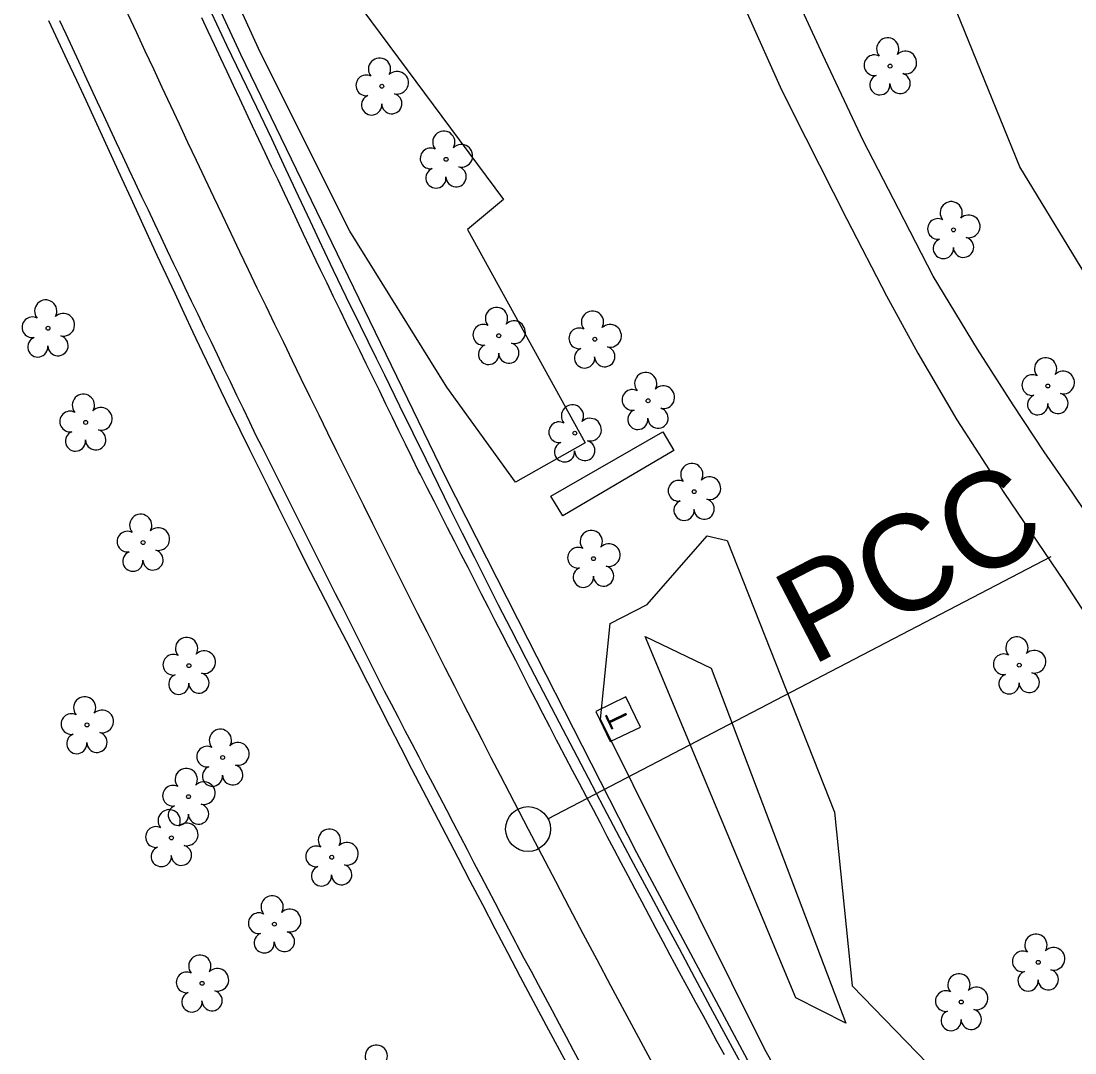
# Model space of a CAD drawing. Extents: x 474972 to 479313, y 498315 to 502691.
# Drawn here: x 475995.1 to 476171.4, y 501439.4 to 501612 of the extents above; entities that cross this region are included whole.
import ezdxf

# ---------------------------------------------------------------- set-up
doc = ezdxf.new("R2010")
doc.units = 0
for name, color, linetype in [('Exist Guardrail', 7, 'Continuous'), ('Exist Horizontal Alignment', 7, 'Continuous'), ('Exist Other Culture Area Outline', 7, 'Continuous'), ('Exist Roads EOP', 7, 'Continuous'), ('Exist Roads EOT', 7, 'Continuous'), ('Exist Roads Soil', 7, 'Continuous'), ('Exist Utilities Telephone Pedestal CELL', 7, 'Continuous'), ('Exist Vegetation Hedge Row', 7, 'Continuous'), ('Exist Vegetation Tree CELL', 7, 'Continuous'), ('Exist Vegetation Woods Line', 7, 'Continuous')]:
    doc.layers.add(name, color=color, linetype=linetype)

msp = doc.modelspace()

# ---------------------------------------------------------------- linework, layer by layer
at = {"layer": 'Exist Guardrail'}
msp.add_lwpolyline([(476022.76, 501626.04), (476031.8, 501606.5), (476046.22, 501576.76), (476066.08, 501535.85), (476079.91, 501508.65), (476098.09, 501472.91), (476116.59, 501438.31), (476140.29, 501395.78), (476158.27, 501364.42), (476168.54, 501347.18), (476182.34, 501324.79), (476193.05, 501307.85), (476195.59, 501304.15)], dxfattribs=at)
at = {"layer": 'Exist Horizontal Alignment'}
msp.add_line((476083.25, 501478.59), (476167.46, 501522.43), dxfattribs=at)
msp.add_circle((476079.93, 501476.86), 3.75, dxfattribs=at)
for centre, radius, start, end in [((478949.91, 502971.03), 3235.64, 203.67637, 207.50231), ((478549.74, 502762.69), 2784.48, 207.50231, 213.99726)]:
    msp.add_arc(centre, radius, start, end, dxfattribs=at)
at = {"layer": 'Exist Other Culture Area Outline'}
msp.add_lwpolyline([(476083.74, 501532.55), (476102.47, 501543.31), (476104.35, 501540.21), (476085.74, 501529.25), (476083.74, 501532.55)], dxfattribs=at)
at = {"layer": 'Exist Roads EOP'}
for points in [[(476026.95, 501613.33), (476029.47, 501608.01), (476031.98, 501602.82), (476034.48, 501597.64), (476036.97, 501592.37), (476039.34, 501587.32), (476041.47, 501582.79), (476043.45, 501578.58), (476045.36, 501574.5), (476047.32, 501570.36), (476049.46, 501565.96), (476051.84, 501561.12), (476053.14, 501558.46), (476054.51, 501555.65), (476055.89, 501552.83), (476058.41, 501547.69), (476060.66, 501543.12), (476062.81, 501538.74), (476064.89, 501534.48), (476066.91, 501530.37), (476068.89, 501526.37), (476070.89, 501522.38), (476072.91, 501518.38), (476074.95, 501514.38), (476077.06, 501510.28), (476079.58, 501505.4), (476081.01, 501502.63), (476082.47, 501499.83), (476085.15, 501494.71), (476087.56, 501490.11), (476090.01, 501485.41), (476092.55, 501480.5), (476095.22, 501475.44), (476097.97, 501470.34), (476100.49, 501465.67), (476102.77, 501461.39), (476105.2, 501456.86), (476107.8, 501452.01), (476110.41, 501447.14), (476113.03, 501442.26), (476115.79, 501437.16)], [(476087.47, 501435.67), (476085.24, 501439.81), (476083.03, 501443.93), (476080.85, 501448.03), (476078.69, 501452.1), (476076.55, 501456.15), (476074.43, 501460.17), (476072.34, 501464.17), (476070.26, 501468.14), (476068.21, 501472.05), (476066.21, 501475.88), (476064.26, 501479.62), (476062.36, 501483.27), (476060.49, 501486.87), (476058.63, 501490.48), (476056.79, 501494.1), (476054.95, 501497.71), (476053.13, 501501.3), (476051.32, 501504.83), (476049.53, 501508.31), (476047.75, 501511.72), (476046.01, 501515.07), (476044.35, 501518.31), (476042.75, 501521.46), (476041.23, 501524.51), (476039.73, 501527.55), (476038.19, 501530.65), (476036.61, 501533.82), (476034.99, 501537.06), (476033.36, 501540.33), (476031.74, 501543.6), (476030.15, 501546.87), (476028.56, 501550.13), (476027, 501553.4), (476025.44, 501556.66), (476023.9, 501559.92), (476022.36, 501563.18), (476020.85, 501566.43), (476019.35, 501569.65), (476017.87, 501572.83), (476016.42, 501575.99), (476014.96, 501579.16), (476013.49, 501582.36), (476012.01, 501585.6), (476010.51, 501588.87), (476009, 501592.16), (476007.49, 501595.46), (476005.96, 501598.77), (476004.42, 501602.08), (476002.87, 501605.4), (476001.31, 501608.73), (475999.73, 501612.07)]]:
    msp.add_lwpolyline(points, dxfattribs=at)
at = {"layer": 'Exist Roads EOT'}
for points in [[(476112.79, 501439.08), (476111.6, 501441.27), (476110.4, 501443.47), (476109.21, 501445.66), (476108.01, 501447.85), (476106.82, 501450.04), (476105.62, 501452.23), (476104.43, 501454.43), (476103.69, 501455.78), (476102.52, 501457.98), (476101.36, 501460.19), (476100.19, 501462.4), (476099.02, 501464.6), (476097.86, 501466.81), (476096.69, 501469.02), (476095.53, 501471.22), (476094.36, 501473.43), (476093.19, 501475.64), (476092.03, 501477.85), (476090.86, 501480.05), (476089.69, 501482.26), (476088.53, 501484.47), (476087.36, 501486.67), (476086.19, 501488.88), (476085.03, 501491.09), (476084.69, 501491.72), (476083.55, 501493.94), (476082.41, 501496.17), (476081.27, 501498.39), (476080.14, 501500.61), (476079, 501502.83), (476077.86, 501505.05), (476076.72, 501507.27), (476075.58, 501509.49), (476074.44, 501511.72), (476073.3, 501513.94), (476072.16, 501516.16), (476071.02, 501518.38), (476069.88, 501520.6), (476068.75, 501522.82), (476067.61, 501525.05), (476066.47, 501527.27), (476065.33, 501529.49), (476064.19, 501531.71), (476063.05, 501533.93), (476061.91, 501536.15), (476061.61, 501536.75), (476060.51, 501538.99), (476059.42, 501541.23), (476058.32, 501543.48), (476057.23, 501545.72), (476056.14, 501547.97), (476055.04, 501550.21), (476053.95, 501552.45), (476052.85, 501554.7), (476051.76, 501556.94), (476050.66, 501559.18), (476049.57, 501561.43), (476048.48, 501563.67), (476047.38, 501565.92), (476046.29, 501568.16), (476045.19, 501570.4), (476044.46, 501571.9), (476043.4, 501574.16), (476042.34, 501576.41), (476041.28, 501578.67), (476040.21, 501580.93), (476039.15, 501583.19), (476038.09, 501585.45), (476037.02, 501587.71), (476035.96, 501589.97), (476034.9, 501592.22), (476033.84, 501594.48), (476032.77, 501596.74), (476031.71, 501599), (476030.65, 501601.26), (476029.58, 501603.52), (476028.52, 501605.78), (476027.46, 501608.04), (476026.39, 501610.29), (476025.33, 501612.55)], [(476088.73, 501437.62), (476087.55, 501439.82), (476086.37, 501442.02), (476085.19, 501444.22), (476084.01, 501446.42), (476082.84, 501448.62), (476081.66, 501450.82), (476080.48, 501453.02), (476079.3, 501455.22), (476078.12, 501457.43), (476077.87, 501457.9), (476076.71, 501460.11), (476075.56, 501462.33), (476074.4, 501464.54), (476073.25, 501466.75), (476072.09, 501468.97), (476070.93, 501471.18), (476069.78, 501473.39), (476068.62, 501475.61), (476067.47, 501477.82), (476066.31, 501480.03), (476065.15, 501482.25), (476064, 501484.46), (476062.84, 501486.67), (476061.69, 501488.89), (476060.53, 501491.1), (476059.38, 501493.31), (476058.22, 501495.52), (476057.06, 501497.74), (476055.91, 501499.95), (476055.56, 501500.61), (476054.44, 501502.84), (476053.32, 501505.07), (476052.2, 501507.3), (476051.08, 501509.53), (476049.97, 501511.77), (476048.85, 501514), (476047.73, 501516.23), (476046.61, 501518.46), (476045.49, 501520.69), (476044.37, 501522.92), (476043.25, 501525.15), (476042.13, 501527.39), (476041.01, 501529.62), (476039.89, 501531.85), (476038.77, 501534.08), (476037.65, 501536.31), (476036.53, 501538.54), (476035.41, 501540.77), (476034.45, 501542.67), (476033.37, 501544.92), (476032.29, 501547.17), (476031.2, 501549.42), (476030.12, 501551.67), (476029.04, 501553.92), (476027.95, 501556.17), (476026.87, 501558.42), (476025.79, 501560.67), (476024.71, 501562.92), (476023.62, 501565.17), (476022.54, 501567.42), (476021.46, 501569.67), (476020.65, 501571.35), (476019.58, 501573.61), (476018.52, 501575.87), (476017.45, 501578.13), (476016.39, 501580.39), (476015.32, 501582.65), (476014.26, 501584.9), (476013.2, 501587.16), (476012.13, 501589.42), (476011.07, 501591.68), (476010, 501593.94), (476008.93, 501596.22), (476007.88, 501598.49), (476006.83, 501600.76), (476005.78, 501603.02), (476004.73, 501605.29), (476003.68, 501607.56), (476002.64, 501609.83), (476001.59, 501612.09)]]:
    msp.add_lwpolyline(points, dxfattribs=at)
at = {"layer": 'Exist Roads Soil'}
for points in [[(476092.31, 501684.44), (476097.49, 501666.15), (476104.11, 501645.78), (476110.79, 501627.44), (476116.58, 501613.33), (476122.33, 501600.52), (476126.42, 501592.47), (476133.29, 501578.92), (476139.92, 501566.08), (476145.14, 501556.45), (476151.68, 501545.35), (476159.53, 501533.17), (476169.63, 501518.27), (476173.89, 501511.76), (476178.53, 501503.54), (476182.54, 501493.47), (476185.63, 501482.9), (476188.11, 501472.97), (476191.26, 501459.13), (476193.58, 501451.58), (476195.17, 501443.4), (476197.02, 501430.55)], [(476206.49, 501429.83), (476203.88, 501443.85), (476200.39, 501459.45), (476197.32, 501472.03), (476193.41, 501486.94), (476188.94, 501498.73), (476184.06, 501510.59), (476179.74, 501519.03), (476175.46, 501526.57), (476170.98, 501533.23), (476166.32, 501539.96), (476161.09, 501547.83), (476155.13, 501557.14), (476147.73, 501569.35), (476141.92, 501580.63), (476135.99, 501592.05), (476129.23, 501606.36), (476123.44, 501618.99), (476117.8, 501633.09), (476112.76, 501648.47), (476107.35, 501664.22), (476104.43, 501674.03), (476101.69, 501683.88)]]:
    msp.add_lwpolyline(points, dxfattribs=at)
at = {"layer": 'Exist Utilities Telephone Pedestal CELL'}
msp.add_line((476094.99, 501495.15), (476094.99, 501495.15), dxfattribs=at)
msp.add_lwpolyline([(476098.72, 501493.91), (476096.3, 501498.96), (476091.26, 501496.54), (476093.67, 501491.5), (476098.72, 501493.91)], dxfattribs=at)
at = {"layer": 'Exist Vegetation Hedge Row'}
for points in [[(476033.03, 501643.73), (476049.4, 501617.8), (476075.8, 501582.16), (476069.78, 501577.16), (476089.5, 501541.45), (476077.82, 501534.89), (476066.33, 501550.81), (476050.08, 501576.88), (476035.07, 501606.82), (476022.28, 501634.99)], [(476099.86, 501514.44), (476109.92, 501525.92), (476113.24, 501525.14), (476131.2, 501479.66), (476134.15, 501450.63), (476148.6, 501435.74), (476160.07, 501423.79), (476179.51, 501374.35), (476197.71, 501339.7), (476192.59, 501336.14)], [(476153.24, 501399.51), (476144.79, 501394.84), (476119.49, 501440.08), (476092.07, 501495.27), (476093.69, 501511.25), (476099.86, 501514.44)]]:
    msp.add_lwpolyline(points, dxfattribs=at)
at = {"layer": 'Exist Vegetation Tree CELL'}
for p, q in [((476140.51, 501604.5), (476140.51, 501604.5)), ((476055.46, 501601.13), (476055.46, 501601.13)), ((476066.21, 501588.9), (476066.21, 501588.9)), ((476151.12, 501577.1), (476151.12, 501577.1)), ((475999.6, 501560.64), (475999.6, 501560.64)), ((476075.03, 501559.39), (476075.03, 501559.39)), ((476091.1, 501558.8), (476091.1, 501558.8)), ((476166.91, 501550.98), (476166.91, 501550.98)), ((476100.01, 501548.51), (476100.01, 501548.51)), ((476005.89, 501544.89), (476005.89, 501544.89)), ((476087.75, 501543.09), (476087.75, 501543.09)), ((476107.72, 501533.3), (476107.72, 501533.3)), ((476015.5, 501524.79), (476015.5, 501524.79)), ((476090.88, 501522.1), (476090.88, 501522.1)), ((476023.17, 501504.2), (476023.17, 501504.2)), ((476162.13, 501504.28), (476162.13, 501504.28)), ((476006.12, 501494.28), (476006.12, 501494.28)), ((476028.82, 501488.83), (476028.82, 501488.83)), ((476023.11, 501482.28), (476023.11, 501482.28)), ((476020.25, 501475.38), (476020.25, 501475.38)), ((476047.07, 501472.14), (476047.07, 501472.14)), ((476037.48, 501460.95), (476037.48, 501460.95)), ((476165.31, 501454.56), (476165.31, 501454.56)), ((476025.38, 501451.05), (476025.38, 501451.05)), ((476152.42, 501447.93), (476152.42, 501447.93))]:
    msp.add_line(p, q, dxfattribs=at)
for centre in [(476140.51, 501604.5), (476055.46, 501601.13), (476066.21, 501588.9), (476151.12, 501577.1), (475999.6, 501560.64), (476075.03, 501559.39), (476091.1, 501558.8), (476166.91, 501550.98), (476100.01, 501548.51), (476005.89, 501544.89), (476087.75, 501543.09), (476107.72, 501533.3), (476015.5, 501524.79), (476090.88, 501522.1), (476023.17, 501504.2), (476162.13, 501504.28), (476006.12, 501494.28), (476028.82, 501488.83), (476023.11, 501482.28), (476020.25, 501475.38), (476047.07, 501472.14), (476037.48, 501460.95), (476165.31, 501454.56), (476025.38, 501451.05), (476152.42, 501447.93)]:
    msp.add_circle(centre, 0.326, dxfattribs=at)
for centre, radius, start, end in [((476140.12, 501607.37), 1.86, 330.1651, 219.7134), ((476143.06, 501605.09), 1.9, 257.1011, 134.1999), ((476055.07, 501604), 1.86, 330.1651, 219.7134), ((476137.9, 501604.65), 1.73, 62.6636, 279.3457), ((476058.01, 501601.72), 1.9, 257.1011, 134.1999), ((476052.85, 501601.28), 1.73, 62.6636, 279.3457), ((476138.8, 501601.38), 1.69, 111.5671, 6.231), ((476142.18, 501601.6), 1.7, 181.2822, 74.56), ((476053.75, 501598.01), 1.69, 111.5671, 6.231), ((476057.13, 501598.23), 1.7, 181.2822, 74.56), ((476065.83, 501591.77), 1.86, 330.1651, 219.7134), ((476068.76, 501589.49), 1.9, 257.1011, 134.1999), ((476063.61, 501589.05), 1.73, 62.6636, 279.3457), ((476067.89, 501586), 1.7, 181.2822, 74.56), ((476064.51, 501585.78), 1.69, 111.5671, 6.231), ((476150.74, 501579.97), 1.86, 330.1651, 219.7134), ((476148.52, 501577.26), 1.73, 62.6636, 279.3457), ((476153.67, 501577.69), 1.9, 257.1011, 134.1999), ((476149.42, 501573.98), 1.69, 111.5671, 6.231), ((476152.8, 501574.2), 1.7, 181.2822, 74.56), ((475999.21, 501563.52), 1.86, 330.1651, 219.7134), ((476002.15, 501561.23), 1.9, 257.1011, 134.1999), ((476074.65, 501562.27), 1.86, 330.1651, 219.7134), ((476090.71, 501561.67), 1.86, 330.1651, 219.7134), ((475996.99, 501560.8), 1.73, 62.6636, 279.3457), ((476072.43, 501559.55), 1.73, 62.6636, 279.3457), ((476077.58, 501559.98), 1.9, 257.1011, 134.1999), ((476093.65, 501559.38), 1.9, 257.1011, 134.1999), ((476001.27, 501557.74), 1.7, 181.2822, 74.56), ((476088.49, 501558.95), 1.73, 62.6636, 279.3457), ((475997.89, 501557.52), 1.69, 111.5671, 6.231), ((476073.33, 501556.27), 1.69, 111.5671, 6.231), ((476076.71, 501556.5), 1.7, 181.2822, 74.56), ((476089.39, 501555.67), 1.69, 111.5671, 6.231), ((476092.77, 501555.9), 1.7, 181.2822, 74.56), ((476166.53, 501553.85), 1.86, 330.1651, 219.7134), ((476099.62, 501551.38), 1.86, 330.1651, 219.7134), ((476164.31, 501551.13), 1.73, 62.6636, 279.3457), ((476169.46, 501551.56), 1.9, 257.1011, 134.1999), ((476102.56, 501549.1), 1.9, 257.1011, 134.1999), ((476005.51, 501547.76), 1.86, 330.1651, 219.7134), ((476097.4, 501548.66), 1.73, 62.6636, 279.3457), ((476165.21, 501547.85), 1.69, 111.5671, 6.231), ((476168.59, 501548.08), 1.7, 181.2822, 74.56), ((476008.44, 501545.48), 1.9, 257.1011, 134.1999), ((476087.36, 501545.97), 1.86, 330.1651, 219.7134), ((476101.68, 501545.61), 1.7, 181.2822, 74.56), ((476003.29, 501545.04), 1.73, 62.6636, 279.3457), ((476090.3, 501543.68), 1.9, 257.1011, 134.1999), ((476098.3, 501545.39), 1.69, 111.5671, 6.231), ((476007.57, 501541.99), 1.7, 181.2822, 74.56), ((476085.14, 501543.25), 1.73, 62.6636, 279.3457), ((476004.19, 501541.77), 1.69, 111.5671, 6.231), ((476089.42, 501540.19), 1.7, 181.2822, 74.56), ((476086.04, 501539.97), 1.69, 111.5671, 6.231), ((476107.33, 501536.17), 1.86, 330.1651, 219.7134), ((476105.11, 501533.45), 1.73, 62.6636, 279.3457), ((476110.27, 501533.89), 1.9, 257.1011, 134.1999), ((476106.02, 501530.18), 1.69, 111.5671, 6.231), ((476109.39, 501530.4), 1.7, 181.2822, 74.56), ((476015.11, 501527.67), 1.86, 330.1651, 219.7134), ((476012.89, 501524.95), 1.73, 62.6636, 279.3457), ((476018.05, 501525.38), 1.9, 257.1011, 134.1999), ((476090.5, 501524.97), 1.86, 330.1651, 219.7134), ((476093.43, 501522.69), 1.9, 257.1011, 134.1999), ((476013.8, 501521.67), 1.69, 111.5671, 6.231), ((476017.17, 501521.89), 1.7, 181.2822, 74.56), ((476088.28, 501522.25), 1.73, 62.6636, 279.3457), ((476092.56, 501519.2), 1.7, 181.2822, 74.56), ((476089.18, 501518.98), 1.69, 111.5671, 6.231), ((476022.78, 501507.07), 1.86, 330.1651, 219.7134), ((476161.74, 501507.15), 1.86, 330.1651, 219.7134), ((476025.72, 501504.78), 1.9, 257.1011, 134.1999), ((476164.68, 501504.86), 1.9, 257.1011, 134.1999), ((476020.56, 501504.35), 1.73, 62.6636, 279.3457), ((476159.52, 501504.43), 1.73, 62.6636, 279.3457), ((476024.84, 501501.3), 1.7, 181.2822, 74.56), ((476163.8, 501501.38), 1.7, 181.2822, 74.56), ((476021.47, 501501.08), 1.69, 111.5671, 6.231), ((476160.42, 501501.15), 1.69, 111.5671, 6.231), ((476005.73, 501497.15), 1.86, 330.1651, 219.7134), ((476003.51, 501494.43), 1.73, 62.6636, 279.3457), ((476008.67, 501494.87), 1.9, 257.1011, 134.1999), ((476004.41, 501491.16), 1.69, 111.5671, 6.231), ((476007.79, 501491.38), 1.7, 181.2822, 74.56), ((476028.44, 501491.7), 1.86, 330.1651, 219.7134), ((476026.22, 501488.98), 1.73, 62.6636, 279.3457), ((476031.37, 501489.42), 1.9, 257.1011, 134.1999), ((476027.12, 501485.71), 1.69, 111.5671, 6.231), ((476030.5, 501485.93), 1.7, 181.2822, 74.56), ((476022.73, 501485.15), 1.86, 330.1651, 219.7134), ((476020.5, 501482.43), 1.73, 62.6636, 279.3457), ((476025.66, 501482.87), 1.9, 257.1011, 134.1999), ((476019.87, 501478.25), 1.86, 330.1651, 219.7134), ((476021.41, 501479.16), 1.69, 111.5671, 6.231), ((476024.78, 501479.38), 1.7, 181.2822, 74.56), ((476017.65, 501475.53), 1.73, 62.6636, 279.3457), ((476022.8, 501475.97), 1.9, 257.1011, 134.1999), ((476046.68, 501475.01), 1.86, 330.1651, 219.7134), ((476018.55, 501472.26), 1.69, 111.5671, 6.231), ((476021.92, 501472.48), 1.7, 181.2822, 74.56), ((476044.46, 501472.29), 1.73, 62.6636, 279.3457), ((476049.62, 501472.72), 1.9, 257.1011, 134.1999), ((476045.36, 501469.01), 1.69, 111.5671, 6.231), ((476048.74, 501469.24), 1.7, 181.2822, 74.56), ((476037.1, 501463.83), 1.86, 330.1651, 219.7134), ((476034.87, 501461.11), 1.73, 62.6636, 279.3457), ((476040.03, 501461.54), 1.9, 257.1011, 134.1999), ((476035.78, 501457.83), 1.69, 111.5671, 6.231), ((476039.15, 501458.05), 1.7, 181.2822, 74.56), ((476164.92, 501457.43), 1.86, 330.1651, 219.7134), ((476025, 501453.92), 1.86, 330.1651, 219.7134), ((476162.7, 501454.71), 1.73, 62.6636, 279.3457), ((476167.86, 501455.15), 1.9, 257.1011, 134.1999), ((476022.78, 501451.2), 1.73, 62.6636, 279.3457), ((476027.93, 501451.64), 1.9, 257.1011, 134.1999), ((476152.04, 501450.8), 1.86, 330.1651, 219.7134), ((476163.6, 501451.44), 1.69, 111.5671, 6.231), ((476166.98, 501451.66), 1.7, 181.2822, 74.56), ((476154.97, 501448.52), 1.9, 257.1011, 134.1999), ((476023.68, 501447.93), 1.69, 111.5671, 6.231), ((476027.05, 501448.15), 1.7, 181.2822, 74.56), ((476149.82, 501448.08), 1.73, 62.6636, 279.3457), ((476154.09, 501445.03), 1.7, 181.2822, 74.56), ((476150.72, 501444.81), 1.69, 111.5671, 6.231), ((476054.53, 501438.87), 1.86, 330.1651, 219.7134)]:
    msp.add_arc(centre, radius, start, end, dxfattribs=at)
at = {"layer": 'Exist Vegetation Woods Line'}
for points in [[(476141.27, 501661.03), (476170.98, 501652.43), (476193.29, 501622.56), (476219.36, 501537.22), (476233.52, 501505.87), (476224.61, 501499.47), (476199.55, 501526.39), (476162.21, 501587.65), (476145.18, 501629.63), (476141.27, 501661.03)], [(476110.57, 501503.8), (476133.13, 501444.37), (476124.76, 501448.63), (476099.51, 501509.07), (476110.57, 501503.8)]]:
    msp.add_lwpolyline(points, dxfattribs=at)

# ---------------------------------------------------------------- texts
at = {"layer": 'Exist Horizontal Alignment'}
msp.add_text('PCC', height=16, rotation=27.5023, dxfattribs=at).set_placement((476127.29, 501504.02))
at = {"layer": 'Exist Utilities Telephone Pedestal CELL'}
msp.add_text('T', height=3.42, rotation=115.5502, dxfattribs=at).set_placement((476097.02, 501494.87))

doc.saveas('drawing.dxf')
